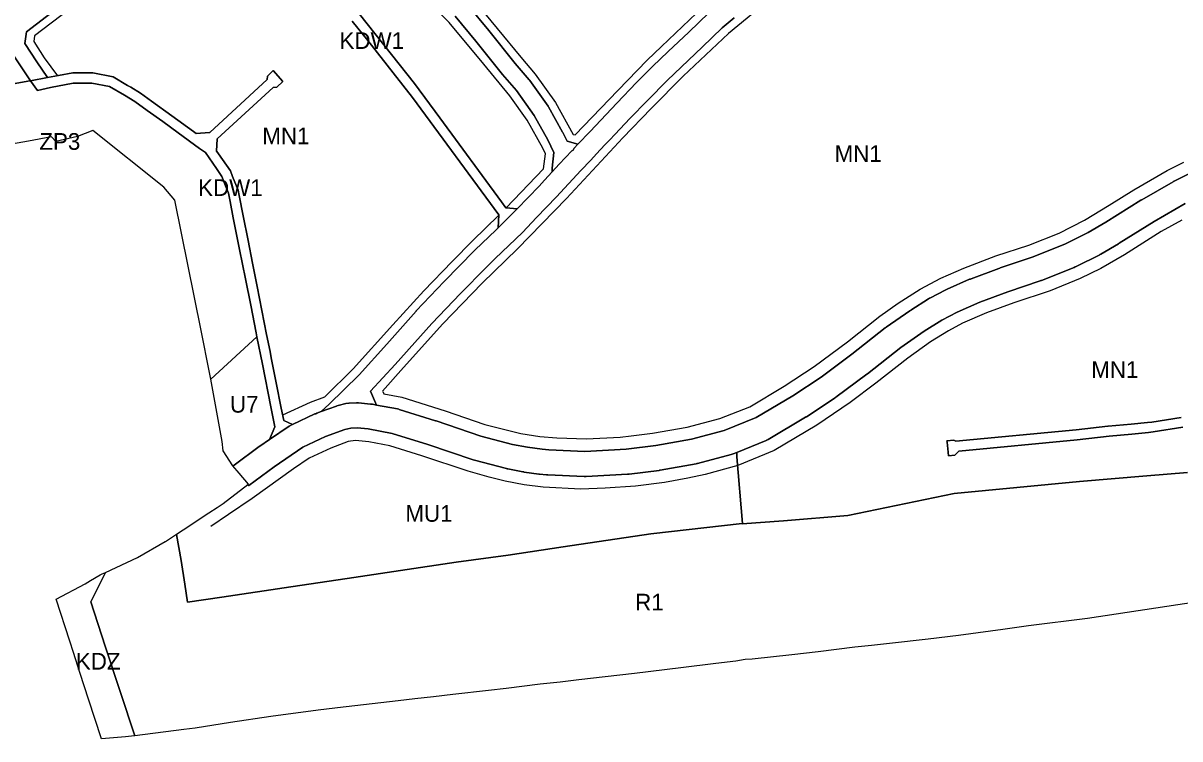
# Model space of a CAD drawing. Extents: x -284239 to -281592, y 34477 to 37267.
# Drawn here: x -283787 to -283094, y 34535 to 34964 of the extents above; entities that cross this region are included whole.
import ezdxf

# ---------------------------------------------------------------- set-up
doc = ezdxf.new("R2010")
doc.units = 0
for name, color, linetype in [('linie_rozgraniczajace', 7, 'Continuous'), ('linie_zabudowy_nieprzekraczalne', 7, 'Continuous'), ('oznaczenia_przeznaczen', 7, 'Continuous')]:
    doc.layers.add(name, color=color, linetype=linetype)

msp = doc.modelspace()

# ---------------------------------------------------------------- linework, layer by layer
at = {"layer": 'linie_rozgraniczajace'}
for points in [[(-283806.652, 34965.834), (-283782.296, 34929.748), (-283783.905, 34929.454), (-283799.023, 34926.616), (-283813.822, 34923.937), (-283828.516, 34921.205), (-283845.172, 34918.155), (-283859.706, 34915.423), (-283870.846, 34913.354), (-283880.181, 34911.63), (-283889.464, 34909.88), (-283897.087, 34923.17), (-283897.116, 34923.218), (-283901.81, 34931), (-283911.001, 34946.396), (-283943, 35000)], [(-283733.394, 34998.539), (-283784.602, 34959.014), (-283785.619, 34952.082), (-283778.461, 34941.083), (-283771.976, 34931.636), (-283782.296, 34929.748), (-283806.652, 34965.834)], [(-283589.568, 34965.359), (-283580.307, 34953.784), (-283553.452, 34919.653), (-283501.738, 34849.434), (-283502.281, 34841.654), (-283503.459, 34840.493), (-283516.289, 34828.157), (-283516.346, 34828.073), (-283516.432, 34828.015), (-283534.508, 34809.431), (-283534.527, 34809.402), (-283534.553, 34809.384), (-283551.275, 34791.815), (-283551.334, 34791.725), (-283551.405, 34791.674), (-283568.972, 34771.991), (-283585.437, 34753.578), (-283585.47, 34753.527), (-283585.67, 34753.302), (-283603.463, 34735.885), (-283608.119, 34731.546), (-283610.841, 34730.561), (-283611.372, 34730.223), (-283611.984, 34730.086), (-283625.399, 34723.786), (-283630.576, 34726.06), (-283632.091, 34733.506), (-283635.115, 34748.651), (-283638.085, 34763.635), (-283638.836, 34767.482), (-283640.843, 34777.772), (-283643.761, 34792.121), (-283646.519, 34806.416), (-283649.331, 34820.341), (-283651.983, 34834.052), (-283654.953, 34848.719), (-283657.34, 34861.052), (-283657.924, 34864.129), (-283661.266, 34872.457), (-283662.592, 34875.666), (-283669.753, 34885.984), (-283670.128, 34886.521), (-283670.784, 34887.461), (-283670.405, 34894.85), (-283636.928, 34925.672), (-283634.812, 34925.804), (-283631.107, 34929.376), (-283636.928, 34935.858), (-283640.368, 34932.419), (-283640.633, 34930.567), (-283674.869, 34898.703), (-283675.028, 34898.684), (-283683, 34898.086), (-283684.711, 34899.324), (-283697.707, 34908.793), (-283709.748, 34917.518), (-283716.379, 34922.346), (-283722.258, 34925.829), (-283724.124, 34926.934), (-283732.717, 34932.079), (-283744.917, 34934.387), (-283756.958, 34934.387), (-283765.499, 34932.822), (-283771.976, 34931.636), (-283778.461, 34941.083), (-283785.619, 34952.082), (-283784.602, 34959.014), (-283733.394, 34998.539)], [(-283520.466, 34974.943), (-283507.888, 34959.86), (-283507.832, 34959.794), (-283491.962, 34939.99), (-283483.599, 34930.32), (-283483.538, 34930.221), (-283483.305, 34929.945), (-283472.313, 34914.477), (-283472.162, 34914.205), (-283472.029, 34914.029), (-283463.604, 34899.022), (-283463.484, 34898.775), (-283463.453, 34898.732), (-283460.94, 34893.477), (-283454.48, 34891.695), (-283456.735, 34889.368)], [(-283376.07, 34970.45), (-283388.003, 34958.933), (-283400.457, 34947.209), (-283409.785, 34938.194), (-283419.321, 34928.658), (-283431.149, 34916.308), (-283447.043, 34899.373), (-283454.48, 34891.695), (-283460.94, 34893.477), (-283463.453, 34898.732), (-283463.484, 34898.775), (-283463.604, 34899.022), (-283472.029, 34914.029), (-283472.162, 34914.205), (-283472.313, 34914.477), (-283483.305, 34929.945), (-283483.538, 34930.221), (-283483.599, 34930.32), (-283491.962, 34939.99), (-283507.832, 34959.794), (-283507.888, 34959.86), (-283520.466, 34974.943)], [(-283608.119, 34731.546), (-283603.463, 34735.885), (-283585.67, 34753.302), (-283585.47, 34753.527), (-283585.437, 34753.578), (-283568.972, 34771.991), (-283551.405, 34791.674), (-283551.334, 34791.725), (-283551.275, 34791.815), (-283534.553, 34809.384), (-283534.527, 34809.402), (-283534.508, 34809.431), (-283516.432, 34828.015), (-283516.346, 34828.073), (-283516.289, 34828.157), (-283503.459, 34840.493), (-283502.281, 34841.654), (-283498.646, 34845.237), (-283494.528, 34849.295), (-283491.973, 34851.814), (-283490.922, 34852.907), (-283477.715, 34866.645), (-283474.501, 34870.09), (-283469.81, 34875.198), (-283465.698, 34879.676), (-283458.09, 34887.701), (-283457.385, 34888.187), (-283456.735, 34889.368), (-283454.48, 34891.695), (-283447.043, 34899.373), (-283431.149, 34916.308), (-283419.321, 34928.658), (-283409.785, 34938.194), (-283400.457, 34947.209), (-283388.003, 34958.933), (-283376.07, 34970.45)], [(-283360.959, 34967.427), (-283368.045, 34961.487), (-283380.031, 34949.919), (-283400.822, 34930.169), (-283412.859, 34917.924), (-283423.437, 34907.137), (-283432.211, 34897.748), (-283435.57, 34894.153), (-283438.289, 34891.244), (-283443.318, 34885.887), (-283446.766, 34882.215), (-283452.723, 34875.872), (-283467.365, 34860.187), (-283479.246, 34847.785), (-283487.74, 34838.874), (-283503.998, 34823.242), (-283509.469, 34817.875), (-283524.737, 34802.294), (-283541.933, 34784.264), (-283548.655, 34776.708), (-283563.975, 34759.617), (-283578.759, 34743.683), (-283575.127, 34735.437), (-283577.565, 34735.893), (-283578.291, 34735.961), (-283578.569, 34736.029), (-283585.775, 34736.684), (-283586.321, 34736.709), (-283586.654, 34736.643), (-283587.012, 34736.708), (-283591.435, 34736.569), (-283591.687, 34736.515), (-283593.386, 34736.307), (-283597.97, 34735.166), (-283598.88, 34734.865), (-283599.005, 34734.844), (-283608.119, 34731.546)], [(-283585.334, 34969.593), (-283552.394, 34928.119), (-283537.18, 34907.416), (-283500.271, 34857.277), (-283497.617, 34853.589), (-283497.493, 34853.573), (-283490.922, 34852.907), (-283491.973, 34851.814), (-283494.528, 34849.295), (-283498.646, 34845.237), (-283502.281, 34841.654), (-283501.738, 34849.434), (-283553.452, 34919.653), (-283580.307, 34953.784), (-283589.568, 34965.359)], [(-283528.014, 34968.381), (-283515.605, 34953.503), (-283499.607, 34933.552), (-283499.587, 34933.519), (-283491.318, 34923.958), (-283480.618, 34908.901), (-283472.404, 34894.269), (-283468.833, 34886.804), (-283469.81, 34877.408), (-283469.81, 34875.198), (-283474.501, 34870.09), (-283477.715, 34866.645), (-283490.922, 34852.907), (-283497.493, 34853.573), (-283497.617, 34853.589), (-283500.271, 34857.277), (-283537.18, 34907.416), (-283552.394, 34928.119), (-283585.334, 34969.593)], [(-283578.759, 34743.683), (-283563.975, 34759.617), (-283548.655, 34776.708), (-283541.933, 34784.264), (-283524.737, 34802.294), (-283509.469, 34817.875), (-283503.998, 34823.242), (-283487.74, 34838.874), (-283479.246, 34847.785), (-283467.365, 34860.187), (-283452.723, 34875.872), (-283446.766, 34882.215), (-283443.318, 34885.887), (-283438.289, 34891.244), (-283435.57, 34894.153), (-283432.211, 34897.748), (-283423.437, 34907.137), (-283412.859, 34917.924), (-283400.822, 34930.169), (-283380.031, 34949.919), (-283368.045, 34961.487), (-283360.959, 34967.427)], [(-283456.735, 34889.368), (-283457.385, 34888.187), (-283458.09, 34887.701), (-283465.698, 34879.676), (-283469.81, 34875.198), (-283469.81, 34877.408), (-283468.833, 34886.804), (-283472.404, 34894.269), (-283480.618, 34908.901), (-283491.318, 34923.958), (-283499.587, 34933.519), (-283499.607, 34933.552), (-283515.605, 34953.503), (-283528.014, 34968.381)], [(-283799.023, 34926.616), (-283783.905, 34929.454), (-283782.296, 34929.748), (-283778.117, 34923.954), (-283770.367, 34925.778), (-283756.617, 34928.36), (-283745.601, 34928.36), (-283734.889, 34926.385), (-283726, 34921.105), (-283719.846, 34917.383), (-283712.325, 34911.951), (-283703.057, 34905.341), (-283693.788, 34898.466), (-283681.025, 34889.235), (-283677.455, 34886.69), (-283670.845, 34877.118), (-283667.654, 34872.37), (-283664.995, 34865.684), (-283663.628, 34862.304), (-283662.716, 34857.441), (-283660.817, 34847.565), (-283657.018, 34828.61), (-283653.524, 34811.023), (-283650.409, 34795.183), (-283647.218, 34778.735), (-283646.704, 34776.192), (-283674.276, 34750.992), (-283675, 34755), (-283680, 34780), (-283695.9, 34858.23), (-283702.42, 34866), (-283745, 34900), (-283754.02, 34896.28), (-283767, 34893.36), (-283769.62, 34896.14), (-283783.45, 34893.5), (-283796.94, 34891.16)], [(-283661, 34699), (-283660.322, 34699.438), (-283645.293, 34710.479), (-283645.099, 34710.588), (-283644.861, 34710.786), (-283639.132, 34714.693), (-283627.281, 34722.775), (-283626.142, 34723.391), (-283625.94, 34723.532), (-283625.399, 34723.786), (-283611.984, 34730.086), (-283611.372, 34730.223), (-283610.841, 34730.561), (-283608.119, 34731.546), (-283599.005, 34734.844), (-283598.88, 34734.865), (-283597.97, 34735.166), (-283593.386, 34736.307), (-283591.687, 34736.515), (-283591.435, 34736.569), (-283587.012, 34736.708), (-283586.654, 34736.643), (-283586.321, 34736.709), (-283585.775, 34736.684), (-283578.569, 34736.029), (-283578.291, 34735.961), (-283577.565, 34735.893), (-283575.127, 34735.437), (-283562.572, 34733.084), (-283561.774, 34732.847), (-283561.41, 34732.792), (-283539.781, 34726.044), (-283539.423, 34725.914), (-283539.354, 34725.903), (-283512.52, 34716.786), (-283493.544, 34711.843), (-283484.6, 34710.121), (-283475.88, 34708.94), (-283471.785, 34708.508), (-283450.23, 34707.544), (-283425.563, 34708.908), (-283407.746, 34711.153), (-283386.508, 34715.002), (-283366.837, 34720.137), (-283347.726, 34727.987), (-283325.816, 34740.997), (-283308.849, 34752.184), (-283290.36, 34765.9), (-283270.438, 34781.612), (-283270.226, 34781.737), (-283269.856, 34782.046), (-283255.627, 34791.964), (-283255.377, 34792.1), (-283255.156, 34792.278), (-283244.518, 34799.084), (-283243.912, 34799.401), (-283243.705, 34799.553), (-283234.214, 34804.541), (-283233.441, 34804.903), (-283219.899, 34810.772), (-283219.426, 34810.87), (-283219.043, 34811.115), (-283202.333, 34817.328), (-283201.904, 34817.406), (-283201.628, 34817.577), (-283182.406, 34824.041), (-283162.884, 34831.742), (-283148.854, 34838.856), (-283138.305, 34845.038), (-283117.354, 34858.186), (-283117.023, 34858.357), (-283116.864, 34858.479), (-283098.098, 34869.231), (-283097.575, 34869.488), (-283097.47, 34869.563), (-283077.823, 34879.372)], [(-283077.823, 34879.372), (-283097.47, 34869.563), (-283097.575, 34869.488), (-283098.098, 34869.231), (-283116.864, 34858.479), (-283117.023, 34858.357), (-283117.354, 34858.186), (-283138.305, 34845.038), (-283148.854, 34838.856), (-283162.884, 34831.742), (-283182.406, 34824.041), (-283201.628, 34817.577), (-283201.904, 34817.406), (-283202.333, 34817.328), (-283219.043, 34811.115), (-283219.426, 34810.87), (-283219.899, 34810.772), (-283233.441, 34804.903), (-283234.214, 34804.541), (-283243.705, 34799.553), (-283243.912, 34799.401), (-283244.518, 34799.084)], [(-283090.756, 34856.145), (-283109.417, 34845.453), (-283130.337, 34832.324), (-283130.613, 34832.181), (-283130.758, 34832.069), (-283141.391, 34825.838), (-283141.92, 34825.575), (-283142.042, 34825.487), (-283156.15, 34818.334), (-283156.71, 34818.2), (-283157.291, 34817.819), (-283176.86, 34810.099), (-283177.37, 34810.003), (-283177.715, 34809.789), (-283197.006, 34803.301), (-283213.88, 34797.027), (-283227.433, 34791.154), (-283236.609, 34786.333), (-283247.059, 34779.647), (-283261.185, 34769.801), (-283281.02, 34754.157), (-283281.151, 34754.08), (-283281.405, 34753.86), (-283299.953, 34740.101), (-283300.214, 34739.953), (-283300.522, 34739.702), (-283317.604, 34728.439), (-283317.935, 34728.263), (-283318.137, 34728.106), (-283340.461, 34714.851), (-283341.359, 34714.401), (-283341.529, 34714.367), (-283341.747, 34714.222), (-283359.341, 34706.995), (-283361.499, 34706.109), (-283362.642, 34705.725), (-283382.84, 34700.452), (-283383.206, 34700.405), (-283383.683, 34700.265), (-283405.16, 34696.373), (-283405.599, 34696.334), (-283405.836, 34696.271), (-283423.871, 34693.999), (-283424.575, 34693.955), (-283424.683, 34693.93), (-283449.495, 34692.558), (-283450.137, 34692.667), (-283450.799, 34692.55), (-283472.463, 34693.52), (-283472.533, 34693.535), (-283473.196, 34693.57), (-283477.383, 34694.011), (-283477.513, 34694.044), (-283477.867, 34694.068), (-283486.661, 34695.259), (-283486.924, 34695.33), (-283487.349, 34695.37), (-283496.495, 34697.132), (-283496.93, 34697.262), (-283497.246, 34697.303), (-283516.482, 34702.313), (-283517.14, 34702.534), (-283517.282, 34702.557), (-283544.285, 34711.732), (-283565.64, 34718.394), (-283580.092, 34721.101), (-283586.733, 34721.705), (-283590.391, 34721.59), (-283594.059, 34720.677), (-283605.669, 34716.476), (-283619.216, 34710.114), (-283636.395, 34698.398), (-283651.573, 34687.248), (-283651.619, 34687.214), (-283652.018, 34687.732), (-283652.059, 34687.786), (-283651.78, 34688), (-283657.297, 34694.582), (-283661, 34699)], [(-283359.341, 34706.995), (-283341.747, 34714.222), (-283341.529, 34714.367), (-283341.359, 34714.401), (-283340.461, 34714.851), (-283318.137, 34728.106), (-283317.935, 34728.263), (-283317.604, 34728.439), (-283300.522, 34739.702), (-283300.214, 34739.953), (-283299.953, 34740.101), (-283281.405, 34753.86), (-283281.151, 34754.08), (-283281.02, 34754.157), (-283261.185, 34769.801), (-283247.059, 34779.647), (-283236.609, 34786.333), (-283227.433, 34791.154), (-283213.88, 34797.027), (-283197.006, 34803.301), (-283177.715, 34809.789), (-283177.37, 34810.003), (-283176.86, 34810.099), (-283157.291, 34817.819), (-283156.71, 34818.2), (-283156.15, 34818.334), (-283142.042, 34825.487), (-283141.92, 34825.575), (-283141.391, 34825.838), (-283130.758, 34832.069), (-283130.613, 34832.181), (-283130.337, 34832.324), (-283109.417, 34845.453), (-283090.756, 34856.145)], [(-283244.518, 34799.084), (-283255.156, 34792.278), (-283255.377, 34792.1), (-283255.627, 34791.964), (-283269.856, 34782.046), (-283270.226, 34781.737), (-283270.438, 34781.612), (-283290.36, 34765.9), (-283308.849, 34752.184), (-283325.816, 34740.997), (-283347.726, 34727.987), (-283366.837, 34720.137), (-283386.508, 34715.002), (-283407.746, 34711.153), (-283425.563, 34708.908), (-283450.23, 34707.544), (-283471.785, 34708.508), (-283475.88, 34708.94), (-283484.6, 34710.121), (-283493.544, 34711.843), (-283512.52, 34716.786), (-283539.354, 34725.903), (-283539.423, 34725.914), (-283539.781, 34726.044), (-283561.41, 34732.792), (-283561.774, 34732.847), (-283562.572, 34733.084), (-283575.127, 34735.437), (-283578.759, 34743.683)], [(-283093.246, 34728.035), (-283110.839, 34725.25), (-283113.423, 34724.954), (-283123.272, 34724.038), (-283137.026, 34722.696), (-283137.064, 34722.693), (-283156.099, 34720.553), (-283228.186, 34713.706), (-283229.357, 34714.444), (-283233.535, 34714.026), (-283233.391, 34713.211), (-283232.824, 34707.238), (-283232.574, 34705.043), (-283228.856, 34705.378), (-283226.383, 34707.85), (-283155.499, 34714.583), (-283155.454, 34714.587), (-283136.416, 34716.728), (-283122.704, 34718.065), (-283112.828, 34718.985), (-283112.773, 34718.99), (-283110.094, 34719.296), (-283110.053, 34719.306), (-283109.965, 34719.313), (-283092.332, 34722.105)], [(-283233.535, 34714.026), (-283229.357, 34714.444), (-283228.186, 34713.706), (-283156.099, 34720.553), (-283137.064, 34722.693), (-283137.026, 34722.696), (-283123.272, 34724.038), (-283113.423, 34724.954), (-283110.839, 34725.25), (-283093.246, 34728.035)], [(-283092.332, 34722.105), (-283109.965, 34719.313), (-283110.053, 34719.306), (-283110.094, 34719.296), (-283112.773, 34718.99), (-283112.828, 34718.985), (-283122.704, 34718.065), (-283136.416, 34716.728), (-283155.454, 34714.587), (-283155.499, 34714.583), (-283226.383, 34707.85), (-283228.856, 34705.378), (-283232.574, 34705.043), (-283232.824, 34707.238), (-283233.391, 34713.211), (-283233.535, 34714.026)], [(-283089.366, 34694.946), (-283113.779, 34692.913), (-283154.085, 34689.622), (-283229.173, 34682.491), (-283292.936, 34669.222), (-283331.268, 34666.097), (-283356.058, 34664.337), (-283356.188, 34664.378), (-283355.953, 34664.404), (-283359.208, 34704.348), (-283359.341, 34706.995)], [(-283084.608, 34617.309), (-283149.24, 34607.51), (-283184.56, 34603.06), (-283200, 34600.94), (-283207.4, 34599.92), (-283226.56, 34597.36), (-283244.82, 34595.1), (-283267.82, 34592.58), (-283278.68, 34591.4), (-283288.62, 34590.32), (-283310.61, 34587.56), (-283326.37, 34585.68), (-283350.12, 34583.1), (-283354.38, 34582.86), (-283359.91, 34581.9), (-283371.93, 34580.55), (-283392.87, 34577.95), (-283420.67, 34574.65), (-283438.16, 34572.56), (-283453.83, 34570.71), (-283465.14, 34569.34), (-283477.09, 34568.2), (-283497.39, 34565.64), (-283508, 34564.43), (-283529.3, 34561.97), (-283540.88, 34560.61), (-283552.04, 34559.36), (-283562, 34558.2), (-283598.37, 34554.02), (-283600, 34553.81), (-283610, 34552.53), (-283638.25, 34548.7), (-283662.51, 34545.21), (-283683.73, 34541.83), (-283690.34, 34540.95), (-283719.713, 34537.237), (-283737.606, 34591.002), (-283746.134, 34617.572), (-283738.629, 34632.657), (-283737.404, 34635.119), (-283718.25, 34644.06), (-283701.56, 34653.56), (-283701.452, 34653.63), (-283694.77, 34657.98), (-283694.764, 34657.946), (-283692.075, 34642.289), (-283689.848, 34628.044), (-283688.305, 34617.259), (-283667.677, 34620.287), (-283626.402, 34626.505), (-283592.667, 34631.565), (-283560.719, 34636.36), (-283527.447, 34641.354), (-283496.227, 34645.555), (-283463.22, 34650.549), (-283410.849, 34658.238), (-283356.188, 34664.378), (-283356.058, 34664.337), (-283331.268, 34666.097), (-283292.936, 34669.222), (-283229.173, 34682.491), (-283154.085, 34689.622), (-283113.779, 34692.913), (-283089.366, 34694.946)]]:
    msp.add_lwpolyline(points, dxfattribs=at)
for points in [[(-283782.296, 34929.748), (-283771.976, 34931.636), (-283765.499, 34932.822), (-283756.958, 34934.387), (-283744.917, 34934.387), (-283732.717, 34932.079), (-283724.124, 34926.934), (-283722.258, 34925.829), (-283716.379, 34922.346), (-283709.748, 34917.518), (-283697.707, 34908.793), (-283684.711, 34899.324), (-283683, 34898.086), (-283675.028, 34898.684), (-283674.869, 34898.703), (-283640.633, 34930.567), (-283640.368, 34932.419), (-283636.928, 34935.858), (-283631.107, 34929.376), (-283634.812, 34925.804), (-283636.928, 34925.672), (-283670.405, 34894.85), (-283670.784, 34887.461), (-283670.128, 34886.521), (-283669.753, 34885.984), (-283662.592, 34875.666), (-283661.266, 34872.457), (-283657.924, 34864.129), (-283657.34, 34861.052), (-283654.953, 34848.719), (-283651.983, 34834.052), (-283649.331, 34820.341), (-283646.519, 34806.416), (-283643.761, 34792.121), (-283640.843, 34777.772), (-283638.836, 34767.482), (-283638.085, 34763.635), (-283635.115, 34748.651), (-283632.091, 34733.506), (-283630.576, 34726.06), (-283625.399, 34723.786), (-283625.94, 34723.532), (-283626.142, 34723.391), (-283627.281, 34722.775), (-283639.132, 34714.693), (-283635.971, 34722.415), (-283638.329, 34734.33), (-283643.419, 34759.932), (-283646.704, 34776.192), (-283647.218, 34778.735), (-283650.409, 34795.183), (-283653.524, 34811.023), (-283657.018, 34828.61), (-283660.817, 34847.565), (-283662.716, 34857.441), (-283663.628, 34862.304), (-283664.995, 34865.684), (-283667.654, 34872.37), (-283670.845, 34877.118), (-283677.455, 34886.69), (-283681.025, 34889.235), (-283693.788, 34898.466), (-283703.057, 34905.341), (-283712.325, 34911.951), (-283719.846, 34917.383), (-283726, 34921.105), (-283734.889, 34926.385), (-283745.601, 34928.36), (-283756.617, 34928.36), (-283770.367, 34925.778), (-283778.117, 34923.954)], [(-283674.276, 34750.992), (-283646.704, 34776.192), (-283643.419, 34759.932), (-283638.329, 34734.33), (-283635.971, 34722.415), (-283639.132, 34714.693), (-283644.861, 34710.786), (-283645.099, 34710.588), (-283645.293, 34710.479), (-283660.322, 34699.438), (-283661, 34699), (-283666.88, 34707.99), (-283667.5, 34713.5)], [(-283694.77, 34657.98), (-283690.862, 34660.572), (-283675.38, 34670.84), (-283670.551, 34674.008), (-283666.86, 34676.43), (-283652.059, 34687.786), (-283652.018, 34687.732), (-283651.619, 34687.214), (-283651.573, 34687.248), (-283636.395, 34698.398), (-283619.216, 34710.114), (-283605.669, 34716.476), (-283594.059, 34720.677), (-283590.391, 34721.59), (-283586.733, 34721.705), (-283580.092, 34721.101), (-283565.64, 34718.394), (-283544.285, 34711.732), (-283517.282, 34702.557), (-283517.14, 34702.534), (-283516.482, 34702.313), (-283497.246, 34697.303), (-283496.93, 34697.262), (-283496.495, 34697.132), (-283487.349, 34695.37), (-283486.924, 34695.33), (-283486.661, 34695.259), (-283477.867, 34694.068), (-283477.513, 34694.044), (-283477.383, 34694.011), (-283473.196, 34693.57), (-283472.533, 34693.535), (-283472.463, 34693.52), (-283450.799, 34692.55), (-283450.137, 34692.667), (-283449.495, 34692.558), (-283424.683, 34693.93), (-283424.575, 34693.955), (-283423.871, 34693.999), (-283405.836, 34696.271), (-283405.599, 34696.334), (-283405.16, 34696.373), (-283383.683, 34700.265), (-283383.206, 34700.405), (-283382.84, 34700.452), (-283362.642, 34705.725), (-283361.499, 34706.109), (-283359.341, 34706.995), (-283359.208, 34704.348), (-283355.953, 34664.404), (-283356.188, 34664.378), (-283410.849, 34658.238), (-283463.22, 34650.549), (-283496.227, 34645.555), (-283527.447, 34641.354), (-283560.719, 34636.36), (-283592.667, 34631.565), (-283626.402, 34626.505), (-283667.677, 34620.287), (-283688.305, 34617.259), (-283689.848, 34628.044), (-283692.075, 34642.289), (-283694.764, 34657.946)], [(-283766.9, 34619.01), (-283749.44, 34628.36), (-283746.24, 34630.37), (-283740.55, 34633.65), (-283739.302, 34634.232), (-283737.404, 34635.119), (-283738.629, 34632.657), (-283746.134, 34617.572), (-283737.606, 34591.002), (-283719.713, 34537.237), (-283721.82, 34536.97), (-283725.3, 34536.66), (-283739.72, 34535.38), (-283747.47, 34559.18), (-283752.48, 34574.65), (-283756.52, 34587.11), (-283758.75, 34593.97)]]:
    msp.add_lwpolyline(points, close=True, dxfattribs=at)
at = {"layer": 'linie_zabudowy_nieprzekraczalne'}
for points in [[(-283497.34, 34853.513), (-283474.973, 34876.892), (-283473.915, 34886.021), (-283475.502, 34889.394), (-283484.762, 34906.195), (-283495.214, 34920.615), (-283510.824, 34939.599), (-283531.462, 34964.734), (-283553.819, 34987.555), (-283564.931, 34998.932), (-283598.269, 35035.643), (-283633.591, 35072.288), (-283643.38, 35083.202), (-283649.863, 35092.991), (-283651.583, 35098.415), (-283651.979, 35100.929), (-283651.45, 35107.147), (-283649.201, 35115.481), (-283646.952, 35122.095), (-283644.042, 35131.554), (-283641.406, 35146.407)], [(-283123.435, 35086.149), (-283128.368, 35084.425), (-283143.846, 35081.746), (-283168.585, 35077.513), (-283186.973, 35071.428), (-283214.49, 35059.191), (-283253.252, 35038.421), (-283271.376, 35028.102), (-283282.356, 35021.289), (-283301.141, 35008.589), (-283317.413, 34996.418), (-283338.58, 34979.419), (-283364.377, 34958.12), (-283391.364, 34932.389), (-283410.547, 34913.207), (-283427.612, 34895.479)], [(-283669.319, 35044.542), (-283695.636, 35023.075), (-283719.581, 35003.363), (-283736.249, 34989.936), (-283759.136, 34972.473), (-283779.773, 34956.598), (-283780.303, 34953.159), (-283774.085, 34943.501), (-283766.025, 34932.756)], [(-283533.455, 34995.065), (-283528.287, 34990.2), (-283516.909, 34978.36), (-283488.731, 34943.964), (-283480, 34933.712), (-283467.829, 34916.646), (-283457.378, 34897.596), (-283456.055, 34897.332), (-283430.655, 34923.988), (-283413.06, 34942.112), (-283404.461, 34950.248), (-283379.326, 34974.325), (-283373.108, 34979.419), (-283348.105, 35000.321), (-283336.596, 35009.317), (-283315.164, 35025.721), (-283306.433, 35031.806), (-283291.494, 35041.235)], [(-283427.612, 34895.612), (-283461.215, 34859.231), (-283490.716, 34828.937), (-283511.75, 34808.497), (-283535.43, 34784.023), (-283558.978, 34757.962), (-283571.414, 34743.674)], [(-283571.281, 34743.608), (-283570.752, 34742.153), (-283559.904, 34740.169), (-283533.975, 34731.967), (-283510.163, 34723.831), (-283488.731, 34718.407), (-283477.222, 34716.555), (-283467.035, 34715.761), (-283449.308, 34715.166), (-283429.2, 34716.224), (-283422.585, 34716.885), (-283409.753, 34718.473), (-283389.115, 34722.243), (-283369.404, 34727.27), (-283351.544, 34734.414), (-283331.039, 34746.651), (-283313.048, 34758.425), (-283292.939, 34773.308), (-283273.757, 34788.654), (-283262.777, 34796.393), (-283249.547, 34804.859), (-283237.244, 34811.474), (-283223.354, 34817.493), (-283204.171, 34824.769), (-283184.46, 34831.252), (-283166.336, 34838.462), (-283151.122, 34846.267), (-283136.438, 34855.13), (-283121.621, 34864.325), (-283101.645, 34875.966), (-283091.591, 34880.861)], [(-283631.087, 34729.555), (-283614.541, 34737.192), (-283606.074, 34740.367), (-283589.009, 34757.036), (-283565.328, 34783.56), (-283546.675, 34803.801), (-283529.742, 34821.528), (-283517.306, 34833.964), (-283501.97, 34849.015)], [(-283092.781, 34846.201), (-283105.217, 34839.321), (-283127.177, 34825.497), (-283141.333, 34817.295), (-283153.636, 34811.209), (-283171.76, 34803.933), (-283193.456, 34796.723), (-283209.728, 34790.638), (-283224.147, 34784.553), (-283232.482, 34779.922), (-283243.33, 34773.308), (-283256.956, 34763.452), (-283276.006, 34748.503), (-283291.484, 34736.861), (-283311.46, 34723.368), (-283336.86, 34708.088), (-283358.688, 34699.092), (-283378.267, 34693.8), (-283388.586, 34691.684), (-283402.609, 34689.104), (-283419.939, 34686.855), (-283438.196, 34685.664), (-283452.748, 34685.069), (-283475.237, 34686.26), (-283486.747, 34687.583), (-283497.992, 34689.832), (-283507.517, 34692.213), (-283520.217, 34695.719), (-283547.866, 34704.979), (-283567.048, 34710.932), (-283579.616, 34713.446), (-283587.553, 34714.239), (-283592.051, 34713.644), (-283602.502, 34709.543), (-283615.467, 34703.59), (-283624.86, 34697.24), (-283649.598, 34679.381), (-283663.621, 34669.856), (-283674.337, 34662.579)], [(-283506.988, 34843.886), (-283506.985, 34843.965)]]:
    msp.add_lwpolyline(points, dxfattribs=at)

# ---------------------------------------------------------------- texts
at = {"layer": 'oznaczenia_przeznaczen'}
for s, p in [('KDW1', (-283597.192, 34948.784)), ('ZP3', (-283776.953, 34888.36)), ('MN1', (-283643.441, 34891.7)), ('MN1', (-283300.759, 34881.112)), ('KDW1', (-283681.88, 34860.684)), ('MN1', (-283147.072, 34751.673)), ('U7', (-283662.782, 34730.869)), ('MU1', (-283557.763, 34665.476)), ('R1', (-283420.198, 34612.307)), ('KDZ', (-283755.088, 34576.882))]:
    msp.add_text(s, height=10, dxfattribs=at).set_placement(p)

doc.saveas('drawing.dxf')
